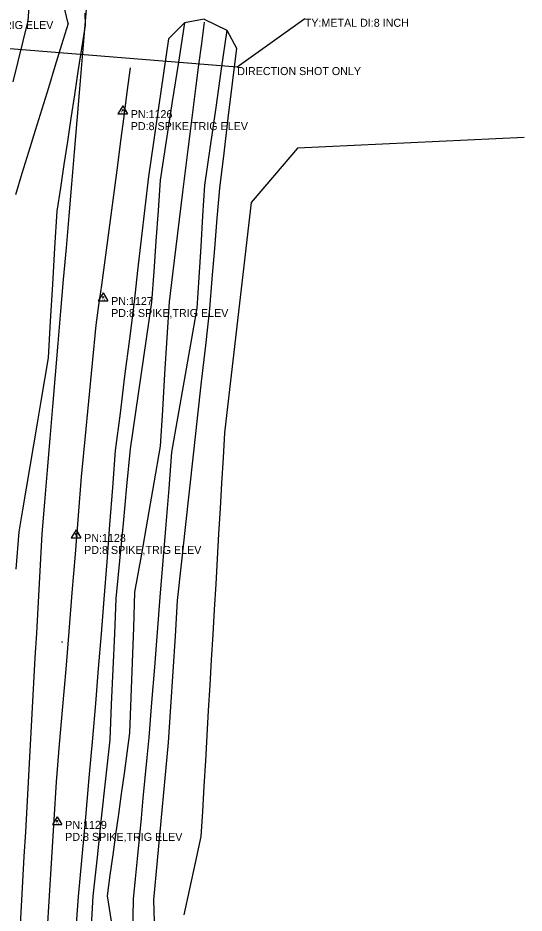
# Model space of a CAD drawing. Extents: x 1445297 to 1476720, y 2042269 to 2057889.
# Drawn here: x 1446336 to 1446652, y 2055534 to 2056093 of the extents above; entities that cross this region are included whole.
import ezdxf

# ---------------------------------------------------------------- set-up
doc = ezdxf.new("R2010")
doc.units = 0
for name, color, linetype in [('S_DITCHLINE', 7, 'Continuous'), ('S_DRG_PT_SYM', 7, 'Continuous'), ('S_LEVEE', 7, 'Continuous'), ('S_MSC_PT_SYM', 7, 'Continuous'), ('S_SECONDARY_CTL', 7, 'Continuous'), ('S_SECONDARY_CTL_ANNOT', 7, 'Continuous'), ('S_SIDE_DRAIN', 7, 'Continuous'), ('S_SIDE_DRAIN_ANNOT', 7, 'Continuous'), ('S_STREAM', 7, 'Continuous'), ('S_TREE', 7, 'Continuous')]:
    doc.layers.add(name, color=color, linetype=linetype)

msp = doc.modelspace()

# ---------------------------------------------------------------- linework, layer by layer
at = {"layer": 'S_DITCHLINE'}
for points in [[(1446366.96, 2056089.97), (1446362.15, 2056110.38), (1446357.34, 2056130.79), (1446352.53, 2056151.2), (1446347.72, 2056171.61)], [(1446343.27, 2056111.56), (1446341.79, 2056091.55), (1446338.67, 2056078.84), (1446335.55, 2056066.14), (1446332.43, 2056053.43)], [(1446366.96, 2056089.97), (1446362.83, 2056076.58), (1446358.71, 2056063.19), (1446354.58, 2056049.79), (1446350.45, 2056036.4), (1446346.33, 2056023.01), (1446342.2, 2056009.61), (1446338.08, 2055996.22), (1446333.95, 2055982.83)], [(1446439.51, 2056090.27), (1446435.74, 2056065.73), (1446431.96, 2056041.19), (1446428.18, 2056016.66), (1446424.4, 2055992.12), (1446423.05, 2055973.06), (1446421.7, 2055953.99), (1446420.35, 2055934.93), (1446419, 2055915.87), (1446415.66, 2055892.98), (1446412.33, 2055870.1), (1446409, 2055847.22), (1446405.66, 2055824.34), (1446403.43, 2055800.95), (1446401.19, 2055777.57), (1446398.96, 2055754.18), (1446396.72, 2055730.8), (1446395.77, 2055708.71), (1446394.81, 2055686.62), (1446393.85, 2055664.53), (1446392.89, 2055642.44), (1446390.26, 2055618.02), (1446387.62, 2055593.59), (1446384.98, 2055569.17), (1446382.34, 2055544.75), (1446381.11, 2055522.59)], [(1446451.81, 2056090.71), (1446450.12, 2056077.45), (1446448.43, 2056064.19), (1446446.74, 2056050.93), (1446445.05, 2056037.67), (1446443.35, 2056024.41), (1446441.66, 2056011.15), (1446439.97, 2055997.89), (1446438.28, 2055984.63), (1446436.19, 2055967.51), (1446434.09, 2055950.4), (1446432, 2055933.28), (1446429.91, 2055916.17), (1446428.54, 2055893.6), (1446427.18, 2055871.04), (1446425.82, 2055848.48), (1446424.45, 2055825.92), (1446420.45, 2055803.1), (1446416.44, 2055780.28), (1446412.44, 2055757.46), (1446408.43, 2055734.64), (1446407.66, 2055712.7), (1446406.89, 2055690.76), (1446406.11, 2055668.83), (1446405.34, 2055646.89), (1446403.59, 2055634.16), (1446401.83, 2055621.44), (1446400.08, 2055608.71), (1446398.32, 2055595.98), (1446396.57, 2055583.26), (1446394.81, 2055570.53), (1446393.06, 2055557.81), (1446391.31, 2055545.08), (1446394.35, 2055525.22)], [(1446466, 2056085.77), (1446462.54, 2056061.58), (1446459.07, 2056037.4), (1446455.61, 2056013.22), (1446452.15, 2055989.03), (1446450.93, 2055969.81), (1446449.71, 2055950.58), (1446448.48, 2055931.35), (1446447.26, 2055912.13), (1446443.33, 2055889.65), (1446439.4, 2055867.17), (1446435.46, 2055844.69), (1446431.53, 2055822.21), (1446429.7, 2055799.55), (1446427.87, 2055776.88), (1446426.03, 2055754.21), (1446424.2, 2055731.55), (1446422.48, 2055709.65), (1446420.75, 2055687.75), (1446419.02, 2055665.86), (1446417.3, 2055643.96), (1446416.08, 2055631.33), (1446414.86, 2055618.7), (1446413.65, 2055606.07), (1446412.43, 2055593.43), (1446411.21, 2055580.8), (1446409.99, 2055568.17), (1446408.78, 2055555.54), (1446407.56, 2055542.91), (1446407.08, 2055521.07)]]:
    msp.add_lwpolyline(points, dxfattribs=at)
at = {"layer": 'S_DRG_PT_SYM'}
for points in [[(1446514.7, 2056092.9), (1446514.7, 2056092.95), (1446514.7, 2056092.9), (1446514.65, 2056092.9), (1446514.7, 2056092.9), (1446514.7, 2056092.85), (1446514.7, 2056092.9), (1446514.75, 2056092.9)], [(1446472.55, 2056062.73), (1446472.55, 2056062.78), (1446472.55, 2056062.73), (1446472.5, 2056062.73), (1446472.55, 2056062.73), (1446472.55, 2056062.68), (1446472.55, 2056062.73), (1446472.6, 2056062.73)]]:
    msp.add_lwpolyline(points, dxfattribs=at)
at = {"layer": 'S_LEVEE'}
msp.add_lwpolyline([(1446405.6, 2056062.16), (1446403.63, 2056046.99), (1446401.66, 2056031.83), (1446399.69, 2056016.67), (1446397.72, 2056001.51), (1446396.04, 2055989.01), (1446394.36, 2055976.51), (1446392.69, 2055964.01), (1446391.01, 2055951.51), (1446389.33, 2055939.02), (1446387.65, 2055926.52), (1446385.98, 2055914.02), (1446384.3, 2055901.52), (1446382, 2055877.81), (1446379.7, 2055854.09), (1446377.4, 2055830.38), (1446375.1, 2055806.67), (1446373.18, 2055782.52), (1446371.25, 2055758.37), (1446369.32, 2055734.23), (1446367.4, 2055710.08), (1446365.38, 2055686.63), (1446363.37, 2055663.18), (1446361.36, 2055639.72), (1446359.35, 2055616.27), (1446357.93, 2055592.53), (1446356.5, 2055568.79), (1446355.08, 2055545.05), (1446353.66, 2055521.31)], dxfattribs=at)
at = {"layer": 'S_MSC_PT_SYM'}
msp.add_lwpolyline([(1446363.1, 2055703.55), (1446363.1, 2055703.6), (1446363.1, 2055703.55), (1446363.05, 2055703.55), (1446363.1, 2055703.55), (1446363.1, 2055703.5), (1446363.1, 2055703.55), (1446363.15, 2055703.55)], dxfattribs=at)
at = {"layer": 'S_SECONDARY_CTL'}
for p, q in [((1446401.02, 2056038.45), (1446398.01, 2056033.49)), ((1446401.02, 2056038.45), (1446403.97, 2056033.49)), ((1446398.01, 2056033.49), (1446403.97, 2056033.49)), ((1446388.77, 2055921.69), (1446385.76, 2055916.73)), ((1446388.77, 2055921.69), (1446391.71, 2055916.73)), ((1446385.76, 2055916.73), (1446391.71, 2055916.73)), ((1446371.92, 2055773.68), (1446368.91, 2055768.72)), ((1446371.92, 2055773.68), (1446374.87, 2055768.72)), ((1446368.91, 2055768.72), (1446374.87, 2055768.72)), ((1446360.08, 2055594.44), (1446357.07, 2055589.48)), ((1446360.08, 2055594.44), (1446363.03, 2055589.48)), ((1446357.07, 2055589.48), (1446363.03, 2055589.48))]:
    msp.add_line(p, q, dxfattribs=at)
for centre, radius in [((1446401.02, 2056035.84), 0.311), ((1446401.02, 2056035.84), 0.183), ((1446401.02, 2056035.84), 0.103), ((1446388.77, 2055919.08), 0.311), ((1446388.77, 2055919.08), 0.183), ((1446388.77, 2055919.08), 0.103), ((1446371.92, 2055771.07), 0.311), ((1446371.92, 2055771.07), 0.183), ((1446371.92, 2055771.07), 0.103), ((1446360.08, 2055591.83), 0.311), ((1446360.08, 2055591.83), 0.183), ((1446360.08, 2055591.83), 0.103)]:
    msp.add_circle(centre, radius, dxfattribs=at)
at = {"layer": 'S_SIDE_DRAIN'}
for p, q in [((1446514.7, 2056092.9), (1446472.55, 2056062.73)), ((1446472.55, 2056062.73), (1446138.31, 2056089.75))]:
    msp.add_line(p, q, dxfattribs=at)
at = {"layer": 'S_STREAM'}
for points in [[(1446377.28, 2056096.35), (1446377.45, 2056088.93), (1446375.25, 2056074.41), (1446373.05, 2056059.89), (1446370.85, 2056045.37), (1446368.65, 2056030.85), (1446366.45, 2056016.33), (1446364.25, 2056001.81), (1446362.05, 2055987.29), (1446359.85, 2055972.77), (1446358.48, 2055949.85), (1446357.11, 2055926.92), (1446355.74, 2055904), (1446354.37, 2055881.07), (1446352.09, 2055867.5), (1446349.81, 2055853.92), (1446347.52, 2055840.35), (1446345.24, 2055826.77), (1446342.96, 2055813.2), (1446340.68, 2055799.63), (1446338.4, 2055786.05), (1446336.12, 2055772.48), (1446334.34, 2055749.08)], [(1446451.82, 2056092.75), (1446439.51, 2056090.27), (1446429.57, 2056080.41), (1446426.46, 2056058.9), (1446423.36, 2056037.4), (1446420.25, 2056015.89), (1446417.15, 2055994.38), (1446414.87, 2055974.81), (1446412.6, 2055955.24), (1446410.33, 2055935.67), (1446408.05, 2055916.1), (1446405.14, 2055892.9), (1446402.22, 2055869.7), (1446399.31, 2055846.49), (1446396.39, 2055823.29), (1446394.61, 2055800.07), (1446392.84, 2055776.85), (1446391.06, 2055753.63), (1446389.29, 2055730.41), (1446387.51, 2055708.67), (1446385.73, 2055686.94), (1446383.95, 2055665.21), (1446382.17, 2055643.47), (1446379.92, 2055618.75), (1446377.66, 2055594.03), (1446375.41, 2055569.31), (1446373.16, 2055544.58), (1446371.43, 2055521.95)], [(1446451.82, 2056092.75), (1446466, 2056085.77), (1446472.03, 2056074.64), (1446469.39, 2056052.77), (1446466.74, 2056030.91), (1446464.1, 2056009.04), (1446461.45, 2055987.17), (1446459.87, 2055968.29), (1446458.28, 2055949.4), (1446456.69, 2055930.51), (1446455.11, 2055911.63), (1446452.61, 2055888.86), (1446450.1, 2055866.09), (1446447.6, 2055843.32), (1446445.1, 2055820.54), (1446442.59, 2055797.77), (1446440.09, 2055775), (1446437.59, 2055752.23), (1446435.08, 2055729.46), (1446433.67, 2055707.3), (1446432.25, 2055685.13), (1446430.83, 2055662.96), (1446429.41, 2055640.8), (1446427.11, 2055616.21), (1446424.8, 2055591.62), (1446422.5, 2055567.03), (1446420.19, 2055542.44), (1446420.72, 2055528.79)]]:
    msp.add_lwpolyline(points, dxfattribs=at)
at = {"layer": 'S_TREE'}
for points in [[(1446379, 2056108.8), (1446377.32, 2056088.94), (1446375.65, 2056069.08), (1446373.97, 2056049.22), (1446372.29, 2056029.36), (1446370.62, 2056009.49), (1446368.94, 2055989.63), (1446367.26, 2055969.77), (1446365.59, 2055949.91), (1446363.91, 2055930.04), (1446362.23, 2055910.18), (1446360.56, 2055890.32), (1446358.88, 2055870.46), (1446357.2, 2055850.59), (1446355.53, 2055830.73), (1446353.85, 2055810.87), (1446352.17, 2055791.01), (1446350.5, 2055771.14), (1446349.64, 2055755.64), (1446348.78, 2055740.13), (1446347.92, 2055724.62), (1446347.07, 2055709.11), (1446346.21, 2055693.61), (1446345.35, 2055678.1), (1446344.5, 2055662.59), (1446343.64, 2055647.08), (1446342.78, 2055631.58), (1446341.92, 2055616.07), (1446341.07, 2055600.56), (1446340.21, 2055585.05), (1446339.35, 2055569.55), (1446338.5, 2055554.04), (1446337.64, 2055538.53), (1446336.78, 2055523.02)], [(1446651.67, 2056018.74), (1446634, 2056017.92), (1446616.32, 2056017.1), (1446598.64, 2056016.28), (1446580.96, 2056015.46), (1446563.29, 2056014.63), (1446545.61, 2056013.81), (1446527.93, 2056012.99), (1446510.25, 2056012.17), (1446495.78, 2055995.14), (1446481.31, 2055978.11), (1446479.22, 2055960.13), (1446477.14, 2055942.16), (1446475.05, 2055924.18), (1446472.96, 2055906.2), (1446470.88, 2055888.22), (1446468.79, 2055870.25), (1446466.7, 2055852.27), (1446464.62, 2055834.29), (1446463.69, 2055818.52), (1446462.77, 2055802.75), (1446461.85, 2055786.99), (1446460.92, 2055771.22), (1446460, 2055755.45), (1446459.08, 2055739.68), (1446458.15, 2055723.91), (1446457.23, 2055708.15), (1446456.31, 2055692.38), (1446455.38, 2055676.61), (1446454.46, 2055660.84), (1446453.54, 2055645.07), (1446452.61, 2055629.31), (1446451.69, 2055613.54), (1446450.76, 2055597.77), (1446449.84, 2055582), (1446446.31, 2055565.69), (1446442.79, 2055549.39), (1446439.26, 2055533.08)]]:
    msp.add_lwpolyline(points, dxfattribs=at)

# ---------------------------------------------------------------- texts
at = {"layer": 'S_SECONDARY_CTL'}
for p in [(1446399.81, 2056033.83), (1446387.56, 2055917.06), (1446370.71, 2055769.06), (1446358.87, 2055589.81)]:
    msp.add_text('TV', height=1.5, dxfattribs=at).set_placement(p)
at = {"layer": 'S_SECONDARY_CTL_ANNOT'}
for s, p in [('PD:8 SPIKE,TRIG ELEV', (1446284.47, 2056086.5)), ('PN:1126', (1446406.02, 2056030.84)), ('PD:8 SPIKE,TRIG ELEV', (1446406.02, 2056023.34)), ('PN:1127', (1446393.77, 2055914.08)), ('PD:8 SPIKE,TRIG ELEV', (1446393.77, 2055906.58)), ('PN:1128', (1446376.92, 2055766.07)), ('PD:8 SPIKE,TRIG ELEV', (1446376.92, 2055758.57)), ('PN:1129', (1446365.08, 2055586.83)), ('PD:8 SPIKE,TRIG ELEV', (1446365.08, 2055579.33))]:
    msp.add_text(s, height=5, dxfattribs=at).set_placement(p)
at = {"layer": 'S_SIDE_DRAIN_ANNOT'}
for s, p in [('TY:METAL DI:8 INCH', (1446514.7, 2056087.9)), ('DIRECTION SHOT ONLY', (1446472.55, 2056057.73))]:
    msp.add_text(s, height=5, dxfattribs=at).set_placement(p)

doc.saveas('drawing.dxf')
